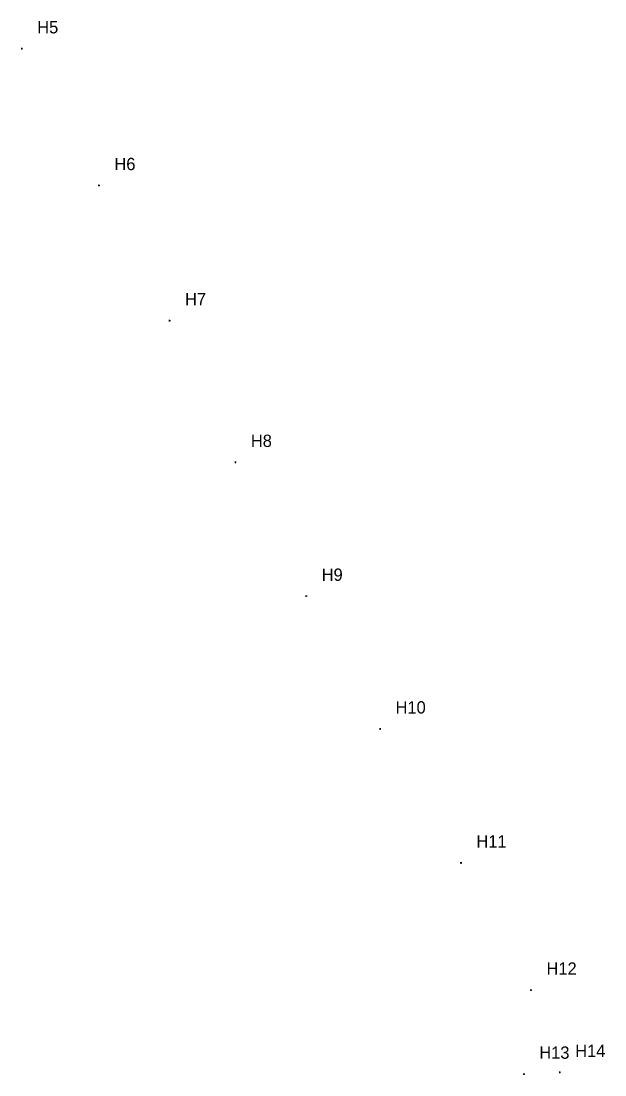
# Model space of a CAD drawing. Extents: x 1727245 to 1729607, y 652704 to 655271.
# Drawn here: x 1727245.2 to 1727434.9, y 654928.7 to 655271.4 of the extents above; entities that cross this region are included whole.
import ezdxf

# ---------------------------------------------------------------- set-up
doc = ezdxf.new("R2010")
doc.units = 0
doc.layers.add('SURVEY - DRAINAGE - Storm Sewer - Points - Locators', color=7, linetype='Continuous')
doc.layers.add('SURVEY - DRAINAGE - Storm Sewer - Points - Numbers', color=7, linetype='Continuous')

msp = doc.modelspace()

# ---------------------------------------------------------------- linework, layer by layer
at = {"layer": 'SURVEY - DRAINAGE - Storm Sewer - Points - Locators'}
for p, q in [((1727245.67, 655262.39), (1727245.17, 655262.39)), ((1727245.42, 655262.14), (1727245.42, 655262.64)), ((1727245.42, 655262.39), (1727245.42, 655262.39)), ((1727245.42, 655262.39), (1727245.42, 655262.39)), ((1727270.74, 655217.91), (1727270.24, 655217.91)), ((1727270.49, 655217.66), (1727270.49, 655218.16)), ((1727270.49, 655217.91), (1727270.49, 655217.91)), ((1727270.49, 655217.91), (1727270.49, 655217.91)), ((1727293.69, 655173.96), (1727293.19, 655173.96)), ((1727293.44, 655173.71), (1727293.44, 655174.21)), ((1727293.44, 655173.96), (1727293.44, 655173.96)), ((1727293.44, 655173.96), (1727293.44, 655173.96)), ((1727315.08, 655127.89), (1727314.58, 655127.89)), ((1727314.83, 655127.64), (1727314.83, 655128.14)), ((1727314.83, 655127.89), (1727314.83, 655127.89)), ((1727314.83, 655127.89), (1727314.83, 655127.89)), ((1727338.1, 655084.35), (1727337.6, 655084.35)), ((1727337.85, 655084.1), (1727337.85, 655084.6)), ((1727337.85, 655084.35), (1727337.85, 655084.35)), ((1727337.85, 655084.35), (1727337.85, 655084.35)), ((1727362.11, 655041.2), (1727361.61, 655041.2)), ((1727361.86, 655040.95), (1727361.86, 655041.45)), ((1727361.86, 655041.2), (1727361.86, 655041.2)), ((1727361.86, 655041.2), (1727361.86, 655041.2)), ((1727388.38, 654997.62), (1727387.88, 654997.62)), ((1727388.13, 654997.37), (1727388.13, 654997.87)), ((1727388.13, 654997.62), (1727388.13, 654997.62)), ((1727388.13, 654997.62), (1727388.13, 654997.62)), ((1727411.16, 654956.25), (1727410.66, 654956.25)), ((1727410.91, 654956), (1727410.91, 654956.5)), ((1727410.91, 654956.25), (1727410.91, 654956.25)), ((1727410.91, 654956.25), (1727410.91, 654956.25)), ((1727408.82, 654928.92), (1727408.32, 654928.92)), ((1727408.57, 654928.67), (1727408.57, 654929.17)), ((1727408.57, 654928.92), (1727408.57, 654928.92)), ((1727408.57, 654928.92), (1727408.57, 654928.92)), ((1727420.49, 654929.51), (1727419.99, 654929.51)), ((1727420.24, 654929.26), (1727420.24, 654929.76)), ((1727420.24, 654929.51), (1727420.24, 654929.51)), ((1727420.24, 654929.51), (1727420.24, 654929.51))]:
    msp.add_line(p, q, dxfattribs=at)

# ---------------------------------------------------------------- texts
at = {"layer": 'SURVEY - DRAINAGE - Storm Sewer - Points - Numbers'}
for s, p in [('H5', (1727250.42, 655267.39)), ('H6', (1727275.49, 655222.91)), ('H7', (1727298.44, 655178.96)), ('H8', (1727319.83, 655132.89)), ('H9', (1727342.85, 655089.35)), ('H10', (1727366.86, 655046.2)), ('H11', (1727393.13, 655002.62)), ('H12', (1727415.91, 654961.25)), ('H13', (1727413.57, 654933.92)), ('H14', (1727425.24, 654934.51))]:
    msp.add_text(s, height=4, dxfattribs=at).set_placement(p)

doc.saveas('drawing.dxf')
